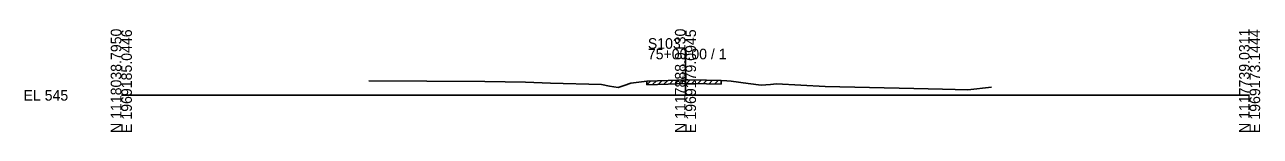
# Model space of a CAD drawing. Extents: x 974 to 1303, y 990 to 14518.
# Drawn here: x 974.3 to 1302.8, y 13990.3 to 14017.5 of the extents above; entities that cross this region are included whole.
import ezdxf

# ---------------------------------------------------------------- set-up
doc = ezdxf.new("R2010")
doc.units = 0
for name, color, linetype in [('Level 10', 7, 'Continuous'), ('Level 60', 7, 'Continuous'), ('Level 61', 7, 'Continuous'), ('Level 63', 7, 'Continuous')]:
    doc.layers.add(name, color=color, linetype=linetype)

msp = doc.modelspace()

# ---------------------------------------------------------------- linework, layer by layer
at = {"layer": 'Level 60'}
for p, q in [((1065.83, 14003.81), (1096.63, 14003.65)), ((1096.63, 14003.65), (1107.42, 14003.46)), ((1107.42, 14003.46), (1114.1, 14003.25)), ((1114.1, 14003.25), (1127.7, 14002.83)), ((1127.7, 14002.83), (1129.76, 14002.44)), ((1129.76, 14002.44), (1132.07, 14002.06)), ((1132.07, 14002.06), (1133.67, 14002.63)), ((1133.67, 14002.63), (1135.46, 14003.2)), ((1135.46, 14003.2), (1137.61, 14003.5)), ((1137.61, 14003.5), (1139.73, 14003.78)), ((1139.73, 14003.78), (1145.43, 14003.96)), ((1145.43, 14003.96), (1150, 14004.1)), ((1150, 14004.1), (1150.6, 14004.12)), ((1150.6, 14004.12), (1155.57, 14004)), ((1155.57, 14004), (1159.48, 14003.93)), ((1159.48, 14003.93), (1160.99, 14003.8)), ((1160.99, 14003.8), (1162.15, 14003.72)), ((1162.15, 14003.72), (1166.64, 14003.13)), ((1166.64, 14003.13), (1170.12, 14002.66)), ((1170.12, 14002.66), (1172.64, 14002.84)), ((1172.64, 14002.84), (1174.18, 14003)), ((1174.18, 14003), (1187.1, 14002.34)), ((1187.1, 14002.34), (1210.73, 14001.84)), ((1225.09, 14001.43), (1231.41, 14002.12)), ((1210.73, 14001.84), (1218.37, 14001.6)), ((1218.37, 14001.6), (1225.09, 14001.43))]:
    msp.add_line(p, q, dxfattribs=at)
at = {"layer": 'Level 61'}
for p, q in [((1139.73, 14002.78), (1140.77, 14003.81)), ((1139.73, 14002.78), (1139.73, 14003.78)), ((1139.73, 14002.78), (1145.43, 14002.96)), ((1139.73, 14002.78), (1139.73, 14002.78)), ((1141.23, 14002.83), (1142.27, 14003.86)), ((1142.73, 14002.87), (1143.77, 14003.91)), ((1144.23, 14002.92), (1145.27, 14003.95)), ((1145.43, 14002.96), (1150, 14003.1)), ((1145.73, 14002.97), (1146.77, 14004)), ((1147.23, 14003.01), (1148.27, 14004.04)), ((1148.73, 14003.06), (1149.77, 14004.09)), ((1150, 14003.1), (1150.6, 14003.12)), ((1150.23, 14003.11), (1151.23, 14004.1)), ((1150.6, 14003.12), (1155.57, 14003)), ((1151.73, 14003.09), (1152.71, 14004.07)), ((1153.23, 14003.06), (1154.21, 14004.03)), ((1154.73, 14003.02), (1155.71, 14004)), ((1155.57, 14003), (1159.48, 14002.93)), ((1156.23, 14002.99), (1157.22, 14003.97)), ((1157.73, 14002.96), (1158.72, 14003.94)), ((1159.48, 14003.93), (1159.48, 14002.93))]:
    msp.add_line(p, q, dxfattribs=at)
at = {"layer": 'Level 63'}
for p, q in [((1150, 14000), (1150, 14012.35)), ((1000, 14000), (1150, 14000)), ((1150, 14000), (1300, 14000))]:
    msp.add_line(p, q, dxfattribs=at)

# ---------------------------------------------------------------- texts
at = {"layer": 'Level 10'}
msp.add_text('549.10', height=0.9, rotation=90, dxfattribs=at).set_placement((1149.95, 14004.6))
at = {"layer": 'Level 63'}
for s, p in [('N 1118038.7950', (1000, 13990)), ('E 1969185.0446', (1002.8, 13990)), ('N 1117888.9130', (1150, 13990)), ('E 1969179.0945', (1152.8, 13990)), ('N 1117739.0311', (1300, 13990)), ('E 1969173.1444', (1302.8, 13990))]:
    msp.add_text(s, height=2.8, rotation=90, dxfattribs=at).set_placement(p)
for s, p in [('S103', (1140, 14012.35)), ('75+00.00 / 1', (1140, 14009.55)), ('EL 545', (974, 13998.6))]:
    msp.add_text(s, height=2.8, dxfattribs=at).set_placement(p)

doc.saveas('drawing.dxf')
